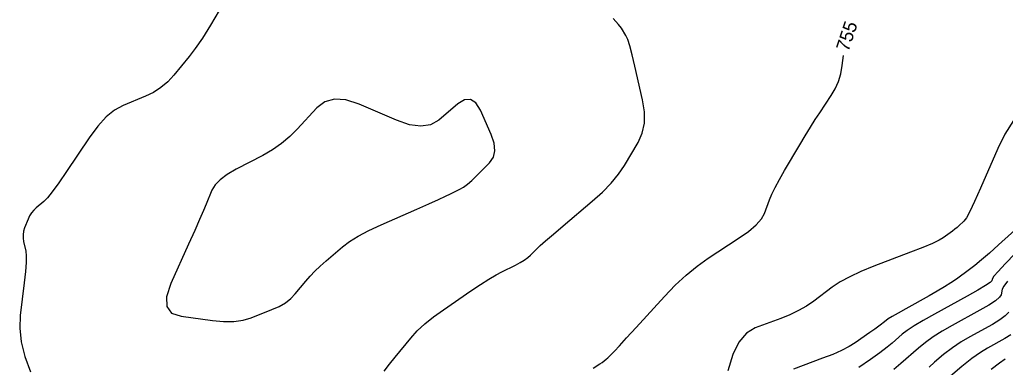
# Model space of a CAD drawing. Extents: x 2079879 to 2092887, y 778083 to 784051.
# Drawn here: x 2084638.2 to 2084844.9, y 780953.6 to 781026.5 of the extents above; entities that cross this region are included whole.
import ezdxf

# ---------------------------------------------------------------- set-up
doc = ezdxf.new("R2010")
doc.units = 0
doc.layers.add('DT_X_Contour_Major', color=7, linetype='Continuous')
doc.layers.add('DT_X_Contour_Minor', color=7, linetype='Continuous')

msp = doc.modelspace()

# ---------------------------------------------------------------- linework, layer by layer
at = {"layer": 'DT_X_Contour_Major'}
for points in [[(2084758.45, 780953.47), (2084759.83, 780954.33), (2084760.33, 780954.65), (2084760.77, 780954.97), (2084761.17, 780955.29), (2084761.51, 780955.6), (2084762.36, 780956.43), (2084762.92, 780957.01), (2084763.96, 780958.13), (2084765.47, 780959.78), (2084767.46, 780961.96), (2084773.41, 780968.48), (2084775.65, 780970.82), (2084777.93, 780972.93), (2084780.24, 780974.82), (2084782.59, 780976.48), (2084788.88, 780980.62), (2084790.99, 780982.11), (2084792.61, 780983.48), (2084793.74, 780984.73), (2084794.37, 780985.85), (2084795.41, 780988.69), (2084795.9, 780989.87), (2084796.59, 780991.29), (2084797.49, 780992.95), (2084798.58, 780994.85), (2084801.76, 781000.21), (2084802.92, 781002.14), (2084804.01, 781003.91), (2084805.03, 781005.51), (2084805.97, 781006.94), (2084808.39, 781010.55), (2084809.22, 781011.96), (2084809.88, 781013.48), (2084810.36, 781015.12), (2084810.69, 781016.88), (2084810.95, 781018.93)], [(2084845.62, 780965.2), (2084844.88, 780964.42), (2084843.72, 780963.55), (2084842.16, 780962.62), (2084837.44, 780960.02), (2084835.65, 780958.96), (2084833.82, 780957.72), (2084831.95, 780956.29), (2084830.03, 780954.68), (2084828.89, 780953.68)]]:
    msp.add_lwpolyline(points, dxfattribs=at)
at = {"layer": 'DT_X_Contour_Minor'}
for points in [[(2084680, 781028.41), (2084678.16, 781025.28), (2084676.49, 781022.62), (2084675.01, 781020.44), (2084673.71, 781018.73), (2084670.49, 781014.81), (2084669.22, 781013.43), (2084667.8, 781012.24), (2084666.25, 781011.23), (2084664.55, 781010.41), (2084659.85, 781008.48), (2084658.09, 781007.52), (2084656.32, 781006.07), (2084654.54, 781004.14), (2084652.76, 781001.72), (2084647.99, 780994.64), (2084646.36, 780992.26), (2084645.02, 780990.41), (2084643.98, 780989.11), (2084643.24, 780988.36), (2084641.66, 780987.06), (2084641.11, 780986.55), (2084640.64, 780985.98), (2084640.25, 780985.36), (2084639.94, 780984.69), (2084639.21, 780982.83), (2084638.99, 780982.12), (2084638.88, 780981.41), (2084638.88, 780980.68), (2084638.99, 780979.95), (2084639.44, 780977.97), (2084639.54, 780977), (2084639.53, 780975.57), (2084639.39, 780973.68), (2084639.13, 780971.33), (2084638.28, 780964.46), (2084638.18, 780961.8), (2084638.51, 780958.95), (2084639.27, 780955.91), (2084640.46, 780952.7)], [(2084714.63, 780952.82), (2084715.7, 780954.27), (2084716.89, 780955.76), (2084720.21, 780959.75), (2084721.56, 780961.24), (2084723.16, 780962.73), (2084724.98, 780964.21), (2084727.03, 780965.68), (2084732.81, 780969.61), (2084734.84, 780970.96), (2084736.6, 780972.08), (2084738.08, 780972.97), (2084739.29, 780973.62), (2084742.15, 780975.05), (2084743.15, 780975.58), (2084744, 780976.1), (2084744.71, 780976.61), (2084745.28, 780977.11), (2084746.6, 780978.44), (2084747.31, 780979.11), (2084748.48, 780980.14), (2084750.1, 780981.53), (2084752.16, 780983.28), (2084758.27, 780988.42), (2084760.41, 780990.33), (2084762.25, 780992.22), (2084763.78, 780994.08), (2084765, 780995.91), (2084767.87, 781000.76), (2084768.73, 781002.68), (2084769.18, 781004.81), (2084769.21, 781007.15), (2084768.82, 781009.69), (2084767.21, 781016.74), (2084766.65, 781019.13), (2084766.14, 781020.99), (2084765.69, 781022.34), (2084765.31, 781023.17), (2084764.36, 781024.69), (2084763.75, 781025.48), (2084762.62, 781026.7)], [(2084730.46, 780990.92), (2084731.23, 780991.38), (2084732.08, 780991.99), (2084732.99, 780992.78), (2084733.99, 780993.73), (2084736.73, 780996.49), (2084737.52, 780997.63), (2084737.84, 780999), (2084737.69, 781000.58), (2084737.07, 781002.39), (2084734.79, 781007.51), (2084733.85, 781009.03), (2084732.75, 781009.75), (2084731.49, 781009.67), (2084730.06, 781008.8), (2084726.05, 781005.4), (2084724.36, 781004.44), (2084722.32, 781004.12), (2084719.93, 781004.43), (2084717.18, 781005.38), (2084709.37, 781008.75), (2084706.61, 781009.65), (2084704.21, 781009.82), (2084702.16, 781009.26), (2084700.46, 781007.96), (2084696.39, 781003.54), (2084694.8, 781001.95), (2084693.06, 781000.5), (2084691.18, 780999.2), (2084689.16, 780998.03), (2084683.59, 780995.12), (2084681.7, 780994.02), (2084680.23, 780992.93), (2084679.16, 780991.83), (2084678.5, 780990.73), (2084677.29, 780987.81), (2084676.72, 780986.46), (2084675.92, 780984.61), (2084674.88, 780982.27), (2084673.6, 780979.42), (2084669.87, 780971.17), (2084668.96, 780968.42), (2084669.01, 780966.36), (2084670.03, 780964.99), (2084672.01, 780964.31), (2084678.58, 780963.41), (2084680.94, 780963.2), (2084683.09, 780963.22), (2084685.02, 780963.49), (2084686.74, 780964.01), (2084691.06, 780965.7), (2084692.58, 780966.38), (2084693.9, 780967.16), (2084695.03, 780968.03), (2084695.97, 780968.99), (2084698.2, 780971.68), (2084699.09, 780972.7), (2084700.1, 780973.74), (2084701.21, 780974.81), (2084702.43, 780975.9), (2084705.85, 780978.83), (2084707.32, 780979.95), (2084709.16, 780981.1), (2084711.39, 780982.28), (2084713.99, 780983.49), (2084721.44, 780986.76), (2084723.98, 780987.88), (2084726, 780988.78), (2084727.51, 780989.47), (2084728.5, 780989.94), (2084730.46, 780990.92)], [(2084846.61, 781005.31), (2084844.81, 781002.47), (2084843.31, 780999.45), (2084839.69, 780991.14), (2084838.45, 780988.38), (2084837.46, 780986.3), (2084836.71, 780984.91), (2084836.2, 780984.22), (2084835.16, 780983.29), (2084834.75, 780982.93), (2084834.31, 780982.57), (2084833.82, 780982.18), (2084833.29, 780981.79), (2084831.84, 780980.73), (2084831, 780980.24), (2084829.58, 780979.58), (2084827.57, 780978.74), (2084824.98, 780977.73), (2084817.3, 780974.8), (2084814.59, 780973.7), (2084812.24, 780972.6), (2084810.24, 780971.51), (2084808.6, 780970.42), (2084804.7, 780967.5), (2084803.17, 780966.46), (2084801.5, 780965.5), (2084799.7, 780964.63), (2084797.77, 780963.85), (2084792.45, 780961.88), (2084790.59, 780960.77), (2084789.01, 780958.9), (2084787.71, 780956.27), (2084786.68, 780952.88)], [(2084848.93, 780984.14), (2084843.48, 780979.26), (2084841.57, 780977.56), (2084839.91, 780976.13), (2084838.5, 780974.98), (2084837.35, 780974.09), (2084834.61, 780972.08), (2084833.48, 780971.3), (2084832.15, 780970.45), (2084830.62, 780969.54), (2084828.89, 780968.56), (2084824.01, 780965.88), (2084822.38, 780964.97), (2084821.14, 780964.26), (2084820.31, 780963.76), (2084819.88, 780963.45), (2084819.26, 780962.91), (2084818.91, 780962.63), (2084818.33, 780962.21), (2084817.53, 780961.63), (2084816.49, 780960.91), (2084813.42, 780958.78), (2084812.12, 780957.97), (2084810.55, 780957.16), (2084808.69, 780956.33), (2084806.54, 780955.5), (2084800.45, 780953.25)], [(2084846.92, 780977.47), (2084844.86, 780975.32), (2084843.38, 780973.72), (2084842.48, 780972.69), (2084842.16, 780972.23), (2084842.06, 780971.73), (2084841.71, 780971.39), (2084840.73, 780970.74), (2084839.11, 780969.79), (2084836.85, 780968.53), (2084830, 780964.76), (2084827.65, 780963.44), (2084825.75, 780962.29), (2084824.29, 780961.32), (2084823.26, 780960.53), (2084821.13, 780958.66), (2084820.1, 780957.82), (2084818.6, 780956.68), (2084816.63, 780955.26), (2084814.19, 780953.56)], [(2084845.34, 780971.65), (2084844.54, 780970.6), (2084844.22, 780969.97), (2084844.01, 780968.82), (2084843.66, 780968.3), (2084842.8, 780967.58), (2084841.41, 780966.67), (2084839.51, 780965.57), (2084833.72, 780962.39), (2084831.65, 780961.2), (2084829.78, 780960), (2084828.12, 780958.81), (2084826.65, 780957.61), (2084823, 780954.41), (2084821.52, 780953.17)], [(2084846.03, 780960.44), (2084844.81, 780959.66), (2084841.16, 780957.65), (2084839.65, 780956.72), (2084837.86, 780955.43), (2084835.78, 780953.77), (2084833.42, 780951.76)], [(2084844.88, 780955.29), (2084843.65, 780954.48), (2084841.89, 780953.14)]]:
    msp.add_lwpolyline(points, dxfattribs=at)

# ---------------------------------------------------------------- texts
at = {"layer": 'DT_X_Contour_Major'}
msp.add_text('755', height=2.8, rotation=71.4145, dxfattribs=at).set_placement((2084811.96, 781019.62))

doc.saveas('drawing.dxf')
